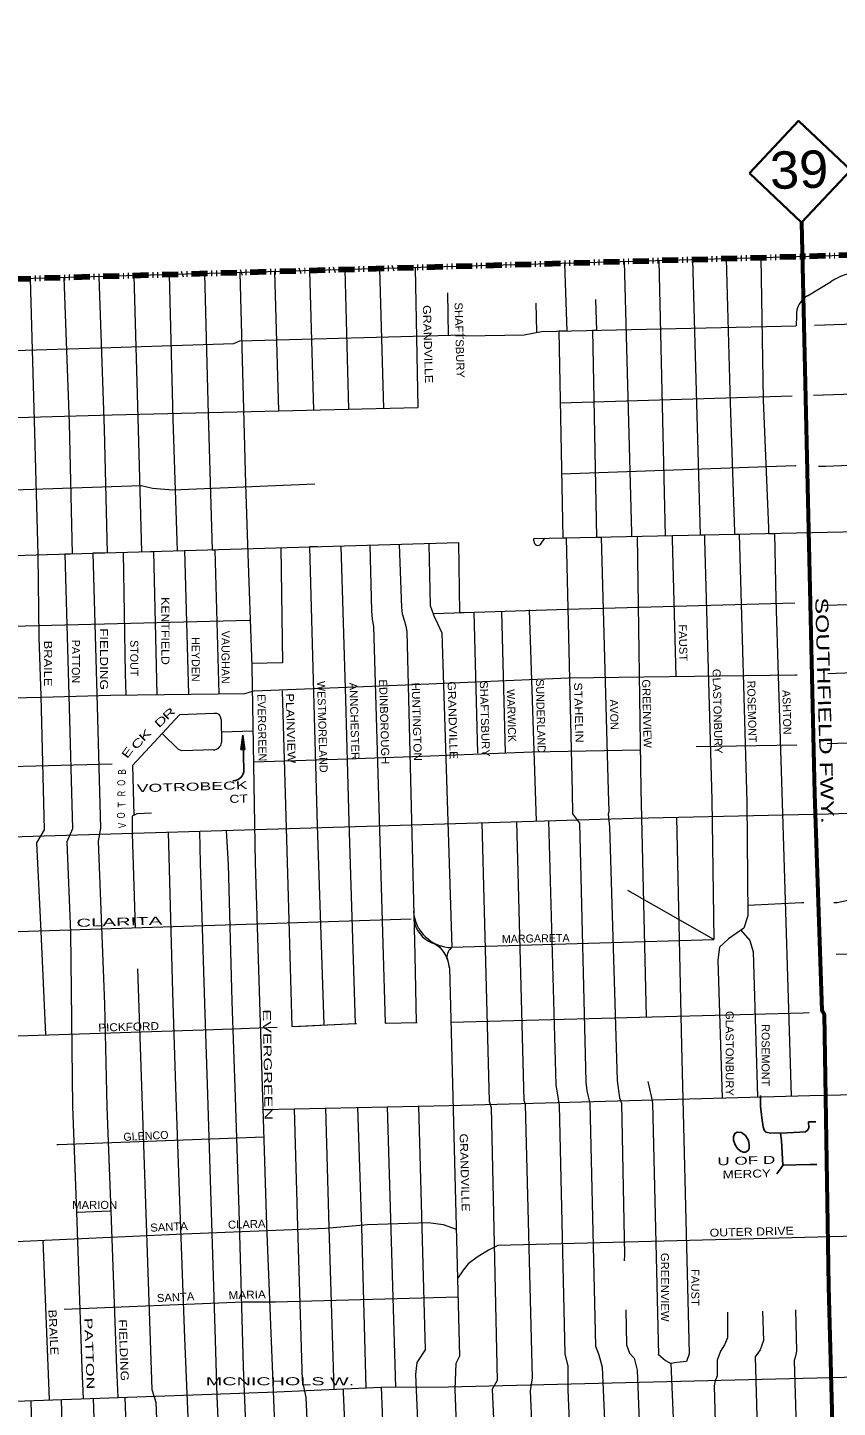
# Model space of a CAD drawing. Extents: x 34705 to 138605, y 34275 to 143551.
# Drawn here: x 45991 to 53584, y 130370 to 143301 of the extents above; entities that cross this region are included whole.
import ezdxf
from ezdxf.enums import TextEntityAlignment as Align

# ---------------------------------------------------------------- set-up
doc = ezdxf.new("R2010")
doc.units = 0
doc.header["$LTSCALE"] = 30
doc.linetypes.add('DASH_DOUBLE_DOT', pattern=[9.2, 5, -1.2, 0.3, -1.2, 0.3, -1.2])
for name, color, linetype, lineweight in [('1', 7, 'Continuous', 13), ('11', 7, 'Continuous', 13), ('51', 7, 'Continuous', 35), ('59', 7, 'DASH_DOUBLE_DOT', 106)]:
    doc.layers.add(name, color=color, linetype=linetype, lineweight=lineweight)

msp = doc.modelspace()

# ---------------------------------------------------------------- linework, layer by layer
at = {"layer": '1'}
for p, q in [((75780.8, 141796.99), (34922.9, 140631.57)), ((48306.3, 141013.31), (48343.1, 139709.21)), ((48635.48, 141022.7), (48673.18, 139716.96)), ((48964.97, 141032.1), (49000.81, 139724.65)), ((49291.42, 141041.41), (49328.1, 139732.34)), ((49624.08, 141050.9), (49648.59, 139739.86)), ((53302.45, 140787.36), (53524.36, 140921.7)), ((49926.71, 140813.88), (49934.1, 140419.05)), ((50755.8, 140719.85), (50761.41, 140450.87)), ((53199.9, 140599.77), (53195.76, 140505.12)), ((50984.96, 139783.51), (53161.09, 139849.98)), ((50739.06, 138489.84), (50738.64, 138513.12)), ((50807.38, 138466.42), (50841.56, 138515.55)), ((50435.47, 137824.62), (50467.43, 136504.62)), ((50694.47, 137843.13), (50759.06, 135863.53)), ((47741.77, 136871.95), (47415.18, 136861.78)), ((47804.8, 136818.37), (47810.05, 136601.48)), ((48104.6, 136706.41), (47807.73, 136697.17)), ((52258.18, 136563.75), (53204.49, 136580.64)), ((47732.72, 136532.67), (47440.7, 136522.67)), ((44160.5, 136331.53), (46784.06, 136401.2)), ((45546.18, 134818.06), (49587.82, 134950.16)), ((49969.83, 134683.25), (52424.28, 134753.75)), ((48468.75, 133940.08), (49062.22, 133966.86)), ((48487.49, 133940.93), (49062.22, 133966.86)), ((49063.21, 133966.91), (49074.02, 133967.39)), ((49342.95, 133972.26), (49643.97, 133976.68)), ((49353.6, 133972.41), (49635.34, 133976.56)), ((49363.34, 133187.43), (49440.76, 130559.91)), ((46132.69, 131936.3), (46192.08, 130444.95)), ((49304.96, 130558.77), (49398.21, 128367.84))]:
    msp.add_line(p, q, dxfattribs=at)
for points in [[(51025.33, 141090.87), (51046.5, 140457.26), (50973.36, 140455.6), (51010.61, 138518.99), (51040.79, 138519.68), (51096.86, 136138.2), (51101.49, 135933.48), (51166.24, 135845.57), (51226.37, 133420.05), (51235.62, 133336.77), (51244.87, 133295.13), (51263.37, 133221.11), (51314.25, 130944.79), (51346.62, 130863.83), (51379, 130748.16), (51490, 128194.25), (51502.9, 127965.17)], [(51584.4, 141106.81), (51651.88, 138567.19), (51652.42, 138532.76), (51707.34, 138534.05), (51739.76, 136161.33), (51790.55, 134029.83)], [(52225.75, 141125.11), (52296.5, 138546.42), (52336.43, 138547.34), (52336.4, 138502.42), (52405.78, 136064.17), (52424.28, 134753.68), (51618.68, 135214.19)], [(51908.83, 141116.07), (51967.67, 138539.4), (52035.33, 138540.73), (52035.77, 138508.21), (52067.87, 137220.45)], [(52542.23, 141134.13), (52578.19, 139785.86), (52618.54, 138576.45), (52618.11, 138553.22), (52664.02, 138554.23), (52734.17, 136041.04), (52743.42, 134978.08), (52706.42, 134862.41), (52563.04, 134760.62), (52479.78, 134681.97), (52461.28, 134561.68), (52503.24, 133270.01)], [(52865.24, 141143.35), (52887.55, 139813.99), (52937.67, 138608.83), (52939.3, 138560.08), (52993.31, 138561.22), (53007.06, 137946.04), (53029.56, 137225.85), (53067.18, 136036.41), (53150.81, 133287.82)], [(46332.08, 140957), (46381.77, 139593.73), (46410.01, 138369.52), (46341.42, 138367.53), (46377.19, 137042.53), (46411.54, 135790.71), (46358.87, 135669.3), (46393.22, 134821.77), (46411.54, 133189.69), (46450.47, 132198.99), (46500.84, 130734.7), (46512.79, 130450.92)], [(46659.77, 140966.34), (46709.22, 139536.46), (46736.52, 138378.98), (46603.01, 138375.11), (46640.53, 137053.99), (46674.88, 135799.87), (46651.98, 135676.17), (46711.51, 134150.61), (46734.41, 133187.4), (46771.05, 132208.15), (46823.72, 130736.99), (46836.05, 130462.6)], [(46987.75, 140975.7), (47027.52, 139534.17), (47059.76, 138388.34), (47170.76, 138391.56), (47203.78, 137049.84)], [(47319.13, 140985.15), (47352.69, 139630.38), (47394.03, 138398.02), (47462.32, 138400), (47498.5, 137053.93)], [(47648.65, 140994.55), (47684.72, 139673.9), (47722.34, 138407.53), (47747.92, 138408.27), (47785.61, 137057.92)], [(47981.66, 141004.05), (48033.09, 139024.1), (48053.24, 138456.35), (48093.94, 137313.03), (48126.32, 135471.37), (48232.15, 132077.43), (48314.67, 129978.44), (48365.06, 128404.34), (48465.85, 125680.25), (48556.56, 122467.79), (48576.72, 121326.61), (48594.36, 121253.51), (48682.55, 117502.92), (48684.81, 117442.73), (48828.7, 111512.8), (48828.7, 111406.94), (48844.83, 109618.16), (48844.83, 109449.36), (48894.21, 107747.71), (49053.86, 101630.72)], [(46014.68, 140947.94), (46054.31, 139506.69), (46086.37, 138358.51), (46095.53, 137585.42), (46113.85, 137037.95), (46145.91, 135781.54), (46074.92, 135660.14), (46113.85, 134828.64), (46157.47, 133860.7)], [(51314.25, 140753.28), (51326.33, 140463.44), (51286.25, 140462.62), (51325.28, 138525.62), (51369.73, 138526.63), (51434.5, 136147.45), (51442.03, 135956.58), (51434.5, 135928.85), (51447.08, 135809.98), (51517.75, 133433.93), (51540.88, 133272), (51559.38, 133221.11), (51587.13, 131800.72), (51585.48, 131742.94)], [(53368.56, 140511.48), (55879.96, 140597.32), (58080.54, 140643.85), (58115.74, 140642.42)], [(42741.68, 140178.77), (46673.59, 140300.71), (47923.59, 140341.42), (47981.73, 140364.69), (50070.38, 140422.85), (50099.45, 140411.21), (50645.96, 140422.85), (50808.75, 140451.93), (53195.76, 140505.12)], [(53359.98, 139856.3), (55906.13, 139940.13), (58521.82, 139992.46)], [(42445.27, 139504.58), (43131.45, 139522.85), (44096.57, 139563.56), (45324.75, 139631.89), (46784.06, 139672.6), (49648.59, 139739.86)], [(53407.25, 139191.2), (53471.54, 139189.89), (55585.98, 139277.23)], [(50998.02, 139119.81), (53186.66, 139195.7), (53194.73, 139195.54)], [(41877.91, 138850.08), (42730.29, 138854.03), (45859.64, 138968.89), (47057.31, 139009.6), (47161.96, 138986.33), (47353.82, 138968.89), (48685.34, 139024.01)], [(50738.64, 138513.12), (57112.52, 138649.02), (58629.96, 138689.73), (63786.92, 138928.18), (63887.95, 138948.95), (67307.74, 138988.33)], [(39362.55, 138216.65), (42747.73, 138278.26), (42858.19, 138266.63), (50030.07, 138474.39)], [(46887.6, 138383.35), (46905.59, 137245.26), (46910.74, 137045.77)], [(48364.02, 138426.12), (48380.8, 137346.78), (48092.96, 137340.53)], [(48708.11, 138435.98), (48635.81, 138433.98), (48705.86, 135824.25), (48767.72, 133957.66)], [(48928.51, 138442.47), (48972.95, 137004.5), (49003.19, 135857.02), (49062.22, 133966.86)], [(49199.5, 138450.32), (49214.85, 137833.77), (49222.41, 137753.11), (49235.01, 137687.58), (49237.53, 137586.75), (49342.95, 133972.26)], [(49476.12, 138458.34), (49497.06, 137866.54), (49504.62, 137806.04), (49522.26, 137748.07), (49537.38, 137690.1), (49547.46, 137642.21), (49620.53, 134608.71), (49635.34, 133976.56)], [(49754.08, 138458.87), (49766.68, 137884.18), (49796.91, 137798.48), (49801.95, 137780.84), (49834.71, 137715.3), (49875.02, 137629.6), (49969.83, 134683.25)], [(50030.07, 138474.39), (50042.04, 137818.94), (50176.61, 137823.27), (50208.83, 136501.4)], [(53453.47, 137889.76), (53487.53, 137887.14), (55382.88, 137951.12), (58519.5, 138038.35), (58641.59, 138009.27), (60552.84, 138098.35)], [(49792.6, 137810.71), (51051.48, 137852.25), (53185.2, 137910.4)], [(41811.68, 137597.81), (42834.94, 137603.62), (42875.64, 137615.25), (48073, 137747.55)], [(41815.64, 137597.83), (42834.94, 137603.62), (42875.64, 137615.25), (48073, 137747.55)], [(53493.37, 137247.58), (55711.36, 137334.64), (56560.19, 137346.27), (58566.01, 137375.35), (58653.22, 137392.8), (59132.32, 137411.52), (59231.7, 137404.43), (59333.45, 137404.43), (60923.56, 137480.03), (61062.26, 137489.13)], [(65163.88, 137331.21), (65305.76, 132788.02), (64749.46, 132412.01), (64626.83, 132338.41), (62738.28, 132301.61), (61417.93, 132272.99), (59451.71, 132146.22), (58797.67, 132105.33), (50401.39, 131888.61), (50311.46, 131843.63), (50205.17, 131778.2), (50123.42, 131716.87), (50074.37, 131655.53), (50021.66, 131579.38)], [(42134.81, 136958.19), (42829.12, 136952.25), (44166.33, 136981.33), (46121.27, 137026.4), (46772.43, 137043.85), (48028.24, 137061.29), (48115.45, 137084.56), (49535.5, 137142.71), (51058.75, 137206.69), (53192.47, 137235.77), (53206.86, 137236.34)], [(48378.29, 137084.53), (48431.21, 135264.68), (48468.75, 133940.08)], [(47415.18, 136861.78), (46973.7, 136386.64), (46988.45, 135920.46)], [(47440.7, 136522.67), (47406.31, 136536.92), (47251.43, 136685.54)], [(53488.97, 136591.27), (56257.87, 136681.82), (58761.09, 136708.21), (58778.75, 136706.01)], [(35050.01, 135441.89), (38867.68, 135617.88), (40146.22, 135653.27), (40348.36, 135643.16), (42072.86, 135638.1), (42926.9, 135633.05), (44579.39, 135678.54), (51671.96, 135890.86), (53501.32, 135931.3), (56282, 136022.29), (57388.72, 136042.52), (58020.4, 136042.52), (61877.48, 136194.17), (62342.4, 136219.45), (65279.74, 136335.71), (66593.65, 136340.77), (68808.33, 136381.21), (71284.55, 136401.43), (76864.35, 136528)], [(48109.66, 136418.65), (48895.96, 136444.83), (49686.66, 136473.91), (50721.54, 136514.62), (51733.15, 136532.68)], [(47152.12, 135938.23), (47014.34, 135932.71), (46970.25, 135910.66), (46970.27, 135747.18), (47000.04, 134863)], [(47852.57, 135776.53), (47870.93, 135457.68), (47906.84, 134178.1), (47936.61, 133279.02), (47973.25, 132219.6), (48012.18, 130750.73), (48090.03, 128810.56), (48096.9, 128422.3), (48026.31, 128308.23)], [(50249.89, 135848.29), (50319.84, 133240.76), (50338.34, 133180.62), (50393.84, 130623.24), (50347.59, 130539.96), (50456.7, 128119.39)], [(50573.64, 135857.98), (50643.6, 133250.02), (50657.47, 133208.38), (50722.23, 130646.38), (50703.73, 130526.08), (50796.23, 128387.42), (50814.73, 128197.73), (50879.48, 127971.02), (50930.36, 127836.85), (50948.86, 127073.45), (50851.73, 126842.12), (50759.23, 126744.96), (50920.25, 119201.95)], [(50874.64, 135866.99), (50944.23, 133393.44), (50962.73, 133277.78), (50976.61, 133199.12), (51027.49, 130873.08), (51055.24, 130757.42), (51055.24, 130535.34), (51166.24, 127961.77)], [(52076.71, 135899.81), (52123.65, 133758.95), (52193.02, 130870.77), (52169.9, 130799.06), (52077.4, 130789.8), (52021.89, 130780.55), (52142.15, 127989.53)], [(47308.76, 135760.25), (47350.4, 134258.27), (47382.45, 133279.02), (47419.09, 132217.31), (47462.6, 131018.74), (47595.41, 127835.9), (47561.07, 127818.72), (47581.67, 126900.18), (47709.91, 122571.45), (47741.39, 121322.48), (47780.32, 119892.55), (47802.67, 119126.89)], [(47601.7, 135769.02), (47610.36, 135470.69), (47650.37, 134155.19), (47677.85, 133301.93), (47748.84, 131000.41), (47764.87, 130472.42), (47849.59, 128573.49), (47775.79, 128444.97)], [(53550.94, 135101.37), (53582.01, 135101.37), (53709.91, 135130.45), (53820.38, 135206.05), (53913.4, 135264.21), (54064.57, 135293.29), (56659.03, 135361.62), (58269.5, 135373.26), (58933.73, 135416.88), (59334.89, 135434.33), (59747.68, 135445.96), (62439.54, 135573.91), (62456.11, 135574.75)], [(52742.56, 135077.17), (53250.61, 135101.37), (53268.59, 135101.37)], [(53573.66, 134618.55), (54656.13, 134649.19), (55260.78, 134672.45), (58438.1, 134727.7), (59256.06, 134755.82), (59712.8, 134788.77), (61852.33, 134881.83), (63031.64, 134946.77)], [(52678.73, 134842.76), (52761.92, 134746.74), (52794.29, 134640.33), (52836.23, 133279.17)], [(49945.58, 134492.76), (50040.7, 130850.55), (50005.42, 130782.5), (49997.86, 130540.52), (50093.61, 127959.47), (50083.53, 127858.64), (50010.46, 127699.85), (49892.03, 127475.52), (49761.01, 127256.23), (49720.69, 127152.26), (49816.44, 124386.57), (49826.52, 124298.35), (49982.74, 118358.02), (49992.82, 118211.82), (50011.81, 117525.07)], [(47021.15, 134479.41), (47155.75, 130537.71), (47192.39, 130418.59), (47293.15, 127855.37), (47279.41, 127795.82), (47452.87, 121666.08), (47468.78, 120842.41)], [(49958.94, 133981.05), (53263.7, 134069.07), (53318.53, 134071.08)], [(42888.29, 133817.39), (44233.19, 133840.79), (45895.98, 133852.42), (47733.19, 133910.58), (48329.89, 133933.82)], [(48198.29, 133162.97), (49942.48, 133199.59), (53326.19, 133292.64), (58792.75, 133413.32), (59827.63, 133471.48), (61398.85, 133544.18), (62741.87, 133608.16), (63962.8, 133660.5), (64165.31, 133663.7)], [(51804.99, 133423.86), (51836.89, 133285.88), (51850.76, 133221.11), (51906.26, 130863.83), (51906.26, 130866.14), (51971.02, 130808.31), (52021.89, 130780.55)], [(49655.33, 133193.56), (49718.17, 130911.05), (49640.06, 130790.06), (49627.46, 130679.15), (49727.69, 128374.34)], [(48490.61, 133169.11), (48521.92, 132064.83), (48566.64, 130621.18), (48599.4, 130464.91), (48647.27, 129406.27), (48674.42, 128632.53)], [(48783.51, 133175.26), (48816.73, 132059.79), (48863.04, 130539.64)], [(49083.3, 133181.55), (49121.62, 132062.31), (49161.15, 130552.54)], [(46266.61, 132834.65), (46278.24, 132834.65), (48208.47, 132904.44)], [(46458.47, 132200.72), (46760.8, 132212.36), (46766.61, 132212.36)], [(42961.39, 131851.77), (45813.13, 131921.56), (47452.66, 131997.17), (48784.05, 132049.51), (49179.4, 132084.41), (49749.17, 132101.86), (49888.7, 132084.41), (50009.64, 132039.84)], [(46333.14, 131291.71), (48010.8, 131358.89), (48316.03, 131360.34), (50026.16, 131407.05)], [(51601, 131284.86), (51605.63, 130956.36), (51633.38, 130877.71), (51679.63, 130831.44), (51707.38, 130720.4), (51813.76, 128017.29), (51850.76, 127961.77), (51855.39, 127545.37), (51804.51, 127420.45), (51716.63, 127290.9), (51642.63, 127142.85), (51596.38, 127013.3), (51591.75, 126902.26), (51591.75, 126758.84), (51559.38, 126638.54), (51485.38, 126490.49), (51420.62, 126337.81), (51434.26, 125327.84)], [(52553.79, 131261.72), (52553.79, 131021.14), (52526.04, 130956.36), (52489.03, 130896.22), (52456.66, 130812.94), (52456.66, 130664.88), (52433.53, 130609.36), (52428.91, 130567.72), (52526.04, 127110.46), (52470.53, 126953.16), (52243.9, 126721.82), (52040.39, 126536.76), (51947.89, 126402.59), (51850.76, 126236.03), (51753.63, 126196.7), (51920.14, 118787.13)], [(52882.17, 131270.98), (52891.42, 130998), (52859.05, 130910.1), (52812.79, 130845.32), (52928.42, 126717.2), (52863.67, 126633.92), (52759.2, 126555.53)], [(53192.06, 131284.86), (53201.31, 130896.22), (53192.06, 130849.95), (53178.18, 130808.31), (53320.03, 126122.33)], [(35186.55, 130231.58), (35458.2, 130231.58), (37489.31, 130321.29), (37869.15, 130321.29), (40074.35, 130374.07), (43172.44, 130363.51), (44385.83, 130374.07), (48329.33, 130516.55), (49305.31, 130558.77), (49933.11, 130564.05), (54929.09, 130685.43), (56976.03, 130759.31), (58131.38, 130785.7), (58991.3, 130812.08), (60184.9, 130901.8), (61393.02, 130975.68), (61503.8, 130980.96), (63404.33, 131007.34), (65002.84, 131017.9), (66400.87, 131039.01), (66997.01, 131039.01), (67635.36, 131075.95), (68722.14, 131123.45), (70126.76, 131153.79)], [(48948.84, 130538.06), (48949.65, 130511.53), (49027.76, 128748.4), (48952.16, 128632.46), (48889.17, 128486.27), (48881.61, 128317.39), (48899.25, 128163.63), (48836.26, 127989.71), (48783.34, 127916.62), (48730.43, 127843.52), (48803.5, 125655.04), (48835.71, 124271.35)], [(46020.86, 130433.14), (46058.89, 128954.88), (46088.66, 127829.03), (46118.43, 126863.52), (46161.94, 125458.79), (46175.68, 125153.57), (46253.53, 122532.51), (46280.44, 121130.07), (46312.5, 119977.3), (46313.03, 119960.43)], [(46307.15, 130443.49), (46347.42, 128911.35), (46390.93, 127829.03), (46422.99, 126856.65), (46466.49, 125447.34), (46477.94, 125249.78), (46477.94, 125142.12), (46558.09, 122546.25), (46584.99, 121146.1), (46621.63, 119963.56)], [(46604.52, 130454.23), (46670.3, 128500.19), (46693.2, 127822.16), (46734.41, 126854.36), (46761.89, 125506.9), (46771.05, 125245.19), (46782.86, 125184.14)], [(46904.05, 130465.06), (46972.56, 128502.48), (46993.17, 127822.16), (47038.97, 126856.65), (47052.71, 126562.88), (47038.97, 126496.45), (47068.74, 125431.31), (47073.32, 125252.07), (47061.87, 125181.06), (47128.27, 122564.58), (47155.18, 121148.39), (47198.27, 119616.41)]]:
    msp.add_lwpolyline(points, dxfattribs=at)
at = {"layer": '1', "lineweight": 25}
for points in [[(52861.57, 133293.94), (52864.26, 133192.17), (52876.67, 133085.1), (52889.01, 133000.14), (52896.23, 132968.63), (52911.4, 132949.88), (52943.63, 132943.97), (53050.63, 132941.54)], [(53050.63, 132941.54), (53054.39, 132941.62), (53231.66, 132948.53), (53285.06, 132952.96), (53307.59, 132970.12), (53316.59, 132991.38), (53314.27, 133046.17), (53380.99, 133045.79)], [(53071.99, 132639.61), (53058.52, 132872.02), (53050.63, 132941.54)], [(53014.77, 132560.39), (53071.97, 132636.75), (53071.99, 132639.61)], [(53071.99, 132639.61), (53325.2, 132645.68), (53390.34, 132647.79)]]:
    msp.add_lwpolyline(points, dxfattribs=at)
msp.add_lwpolyline([(52642.66, 132950.73), (52684.73, 132946.53), (52720.79, 132919.07), (52749.03, 132870.75), (52758.15, 132831.79), (52755.87, 132796.3), (52746.29, 132778.73), (52722.96, 132763.52), (52700.42, 132762.78), (52671.21, 132774.65), (52647.5, 132796.71), (52624.66, 132830.31), (52609.39, 132874.76), (52609.5, 132906.81), (52623.17, 132937.25)], close=True, dxfattribs=at)
at = {"layer": '1'}
for centre, radius, start, end in [((53905.88, 140286.35), 741.1, 98.89147, 120.9842), ((53405.45, 140609.22), 205.77, 120.03585, 182.63222), ((50775.53, 138484.86), 36.8, 172.22211, 329.93779), ((47753.99, 136823.13), 51.03, 354.63969, 106.77835), ((47733.52, 136609.52), 76.85, 269.40101, 353.99619), ((49973.38, 135043.36), 364.16, 183.80563, 269.43567), ((49884.04, 134977.82), 273.12, 189.4637, 248.06821), ((49686.48, 134486.31), 256.6, 1.46558, 68.13943), ((49609.83, 134454.12), 337.96, 6.56485, 48.39621), ((50043.07, 134587.06), 120.9, 127.28276, 182.52679)]:
    msp.add_arc(centre, radius, start, end, dxfattribs=at)
at = {"layer": '11', "lineweight": 25}
for p, q in [((48010.09, 136669), (47991.04, 136535.64)), ((48010.03, 136641.52), (47995.45, 136539.49)), ((48009.96, 136614.03), (47999.87, 136543.33)), ((48009.93, 136586.48), (48004.31, 136547.18)), ((48009.93, 136586.48), (48015.41, 136547.19)), ((48009.96, 136614.03), (48019.8, 136543.36)), ((48010.03, 136641.52), (48024.22, 136539.52)), ((48010.09, 136669), (48028.64, 136535.69)), ((48018.45, 136344.75), (48011.21, 136593.9)), ((48028.64, 136535.69), (47991.04, 136535.64)), ((48024.22, 136539.52), (47995.45, 136539.49)), ((48019.8, 136543.36), (47999.87, 136543.33)), ((48015.41, 136547.19), (48004.31, 136547.18)), ((47916.17, 136241.74), (47921.4, 136241.89))]:
    msp.add_line(p, q, dxfattribs=at)
msp.add_arc((47918.49, 136341.85), 100, 271.66472, 1.66504, dxfattribs=at)
at = {"layer": '51'}
msp.add_lwpolyline([(52758.41, 141937.09), (53219.96, 142426.26), (53709.13, 141964.72), (53247.59, 141475.55)], close=True, dxfattribs=at)
at = {"layer": '51', "lineweight": 60}
msp.add_lwpolyline([(53247.59, 141475.55), (53367.81, 136119.69), (53437.19, 134090.91), (53460.32, 134053.9), (53501.94, 131503.46), (53659.2, 125572.1), (53705.45, 123295.79), (53737.83, 121494.87), (53784.08, 121152.5), (53816.45, 120138.11), (53862.7, 118347.6), (53920.69, 117583.67), (53996.83, 116839.32), (53996.26, 116300.14), (54017.35, 115245.27), (54103.21, 113517.38), (54126.34, 110285.67), (54140.21, 108707.98), (54144.84, 108035.97), (54101.7, 107394.41), (54140.21, 105981.73), (54195.72, 103679.98), (54256.6, 101226.04)], dxfattribs=at)
at = {"layer": '59'}
msp.add_lwpolyline([(131989.06, 109708.72), (126856.28, 120352.83), (127983.73, 120601.28), (129321.71, 120998.46), (130612.42, 121494.12), (133722.19, 123216.65), (134563.84, 124776.42), (136438.38, 130047.1), (136736.54, 131235.05), (136773.12, 131974.15), (125584.57, 138103.26), (128512.62, 143301.1), (34921.35, 140631.52)], dxfattribs=at)

# ---------------------------------------------------------------- texts
at = {"layer": '11'}
for s, height, rotation, width, p in [('GRANDVILLE', 75, 271.653, 1.15, (49707.31, 140333.73)), ('SHAFTSBURY', 75, 271.654, 1.05, (50003.89, 140370.56)), ('KENTFIELD', 75, 270, 1.15, (47246.16, 137646.23)), ('SOUTHFIELD FWY.', 120, 271.584, 1.45, (53404.55, 136898.93)), ('FIELDING', 75, 270, 1.25, (46670.21, 137383.77)), ('FAUST', 75, 271.41, 1.05, (52099.34, 137535.33)), ('BRAILE', 75, 270, 1.2, (46146.16, 137341.55)), ('GLASTONBURY', 75, 271.409, 1.05, (52422.83, 136892.9)), ('ANNCHESTER', 75, 271.654, 1.05, (49018.58, 136798.39)), ('EDINBOROUGH', 75, 271.653, 1.05, (49298.1, 136793.71)), ('HUNTINGTON', 75, 271.653, 1.1, (49602.47, 136794.93)), ('GRANDVILLE', 75, 271.653, 1.15, (49939.58, 136808.44)), ('SHAFTSBURY', 75, 271.654, 1.05, (50241.36, 136821.19)), ('STAHELIN', 75, 271.41, 1.15, (51121.87, 136881.01)), ('GREENVIEW', 75, 271.409, 1.05, (51760.83, 136870.89)), ('PLAINVIEW', 75, 271.654, 1.2, (48421.4, 136732.73)), ('D', 75, 43.259, 1.6, (47264.75, 136772.89)), ('R', 75, 43.259, 1.6, (47341.44, 136845.06)), ('K', 75, 43.259, 1.7, (47117.42, 136643.91)), ('E', 75, 53.966, 1.5, (46955.33, 136485.82)), ('C', 75, 43.259, 1.6, (47046.35, 136567.38)), ('B', 75, 91.345, 0.75, (46913.34, 136326.19)), ('O', 75, 91.345, 0.65, (46906.33, 136224.65)), ('R', 75, 91.345, 0.65, (46908.7, 136123.38)), ('T', 75, 91.345, 0.85, (46911.16, 136018.76)), ('O', 75, 91.345, 0.65, (46904.09, 135919.22)), ('V', 75, 91.345, 0.75, (46915.73, 135824.25)), ('CLARITA', 75, 1.596, 1.9, (46852.2, 134884.2)), ('PICKFORD', 75, 1.595, 1.1, (46939.24, 133899.27)), ('EVERGREEN', 75, 271.007, 1.65, (48205.41, 133580.47)), ('GLASTONBURY', 75, 270, 1.05, (52536.24, 133687.48)), ('GRANDVILLE', 75, 271.653, 1.15, (50052.41, 132570.14)), ('U OF D', 75, 1.665, 1.6, (52730.98, 132646.19)), ('MERCY', 75, 1.665, 1.25, (52734.62, 132521.24)), ('SANTA', 75, 2.793, 1.05, (47318.69, 132025.02)), ('CLARA', 75, 1.612, 1.05, (48046.48, 132049.55)), ('OUTER DRIVE', 75, 1.479, 1.15, (52781.27, 131979.45)), ('GREENVIEW', 75, 270, 1.05, (51928.96, 131496.22)), ('FAUST', 75, 270, 1.05, (52214.03, 131494.1)), ('SANTA', 75, 2.793, 1.05, (47380.74, 131365.48)), ('MARIA', 75, 1.612, 1.1, (48050.82, 131388.18)), ('BRAILE', 75, 272.795, 1.2, (46196.44, 131071.16)), ('PATTON', 75, 271.97, 1.65, (46533.86, 130873.25)), ('FIELDING', 75, 272.05, 1.25, (46855.47, 130905.43))]:
    msp.add_text(s, height=height, rotation=rotation, dxfattribs=dict(at, width=width)).set_placement(p, align=Align.CENTER)
for s, rotation, p in [('VAUGHAN', 270, (47809.3, 137400.46)), ('PATTON', 270, (46406.09, 137360.99)), ('STOUT', 270, (46953.64, 137391.42)), ('HEYDEN', 270, (47530.52, 137380.4)), ('WESTMORELAND', 271.655, (48717.53, 136747.19)), ('WARWICK', 271.654, (50490.6, 136851.87)), ('SUNDERLAND', 271.409, (50765.16, 136847.9)), ('ROSEMONT', 271.409, (52744.85, 136890.2)), ('ASHTON', 271.407, (53072.76, 136883.25)), ('EVERGREEN', 271.007, (48151.81, 136739.22)), ('AVON', 271.411, (51453.69, 136862.4)), ('MARGARETA', 1, (50756.01, 134727.86)), ('ROSEMONT', 270, (52873.16, 133670.83)), ('GLENCO', 2.795, (47102.47, 132877.45))]:
    msp.add_text(s, height=75, rotation=rotation, dxfattribs=at).set_placement(p, align=Align.CENTER)
for s, width, p in [('VOTROBECK', 1.65, (48054.22, 136164.85)), ('CT', 1.3, (48057.86, 136039.9))]:
    msp.add_text(s, height=75, rotation=1.665, dxfattribs=dict(at, width=width)).set_placement(p, align=Align.RIGHT)
for s, width, p in [('MARION', 1.05, (46620.19, 132230.34)), ('MCNICHOLS W.', 1.85, (48357.62, 130577.59))]:
    msp.add_text(s, height=75, dxfattribs=dict(at, width=width)).set_placement(p, align=Align.CENTER)
at = {"layer": '51', "width": 1.05}
msp.add_text('39', height=350, rotation=1.665, dxfattribs=at).set_placement((53230.04, 141795.49), align=Align.CENTER)

doc.saveas('drawing.dxf')
